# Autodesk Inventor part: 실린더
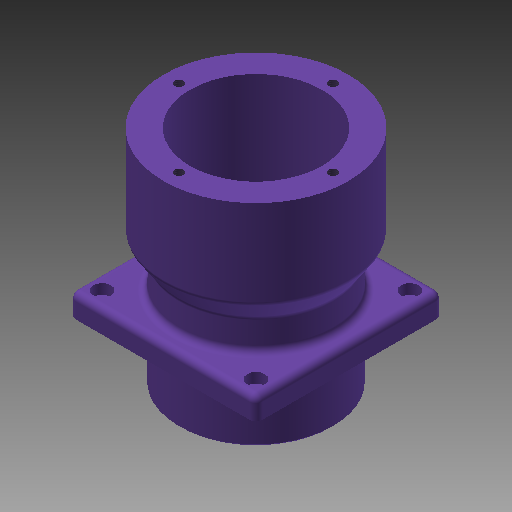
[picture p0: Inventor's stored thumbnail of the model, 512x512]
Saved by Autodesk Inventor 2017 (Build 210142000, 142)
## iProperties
Created: 2016-11
Part Number: 실린더
Material: 알루미늄 6061
Document SubType Name: Modeling
Designer: mduedu
Density: 2.71 g/cm^3
Mass: 568.286 g
Surface Area: 557.364 cm^2
Volume: 209.7 cm^3
Appearance: 보라색
Author: mduedu
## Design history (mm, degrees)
sketch "스케치1"
  geometry: L1 (0, 0)-(0, 101); L2 (30, 0)-(30, 101); L3 (30, 101)-(42, 101); L4 (42, 101)-(42, 61); L5 (42, 61)-(35, 51); L6 (35, 51)-(35, 0); L7 (35, 0)-(30, 0)
  constraints: 14 end point, 4 parallel, 2 horizontal alignment, 1 perpendicular, 1 vertical
  dimensions: "d0" = 101 distance of L1.start L1.end; "d1" = 60 diameter of L2.end L1; "d2" = 84 diameter of L3.end L1; "d3" = 70 diameter of L6.end L1; "d4" = 40 distance of L3.end L4.end; "d5" = 50 vertical distance of L5.end L3.end
revolve "회전1" sketch "스케치1" stored, may be unused: angle "d6" = 90 deg
node "작업 평면1"
sketch "스케치2"
  geometry: L1 (-42.5, -42.5)-(42.5, -42.5); L2 (42.5, -42.5)-(42.5, 42.5); L3 (42.5, 42.5)-(-42.5, 42.5); L4 (-42.5, 42.5)-(-42.5, -42.5); L5 (-42.5, -42.5)-(42.5, 42.5); L6 (42.5, -42.5)-(-42.5, 42.5); C1 r 35 at (0, 0) reference; C2 r 35 at (0, 0); 1 further point
  constraints: 12 end point, 2 midpoint, 2 parallel, 2 perpendicular, 1 centre point, 1 coincident, 1 concentric, 1 horizontal
  dimensions: "d8" = 85 distance of L2.end L3.end
extrude "돌출1" join sketch "스케치2" distance "d10" = 10; taper "d11" = 0 deg
fillet "모깎기1" dims "d12" = 3
fillet "모깎기2" dims "d13" = 3
chamfer "모따기1" distance "d14" = 1; stored, may be unused: second distance "d15" = 2, angle "d16" = 45 deg
chamfer "모따기2" distance "d17" = 5; stored, may be unused: second distance "d18" = 2, angle "d19" = 15 deg
sketch "스케치3"
  geometry: L1 (-35, -35)-(35, -35); L2 (35, -35)-(35, 35); L3 (35, 35)-(-35, 35); L4 (-35, 35)-(-35, -35); L5 (-35, -35)-(35, 35); L6 (35, -35)-(-35, 35); 5 further points
  constraints: 12 end point, 4 coincident, 2 midpoint, 2 parallel, 1 horizontal, 1 perpendicular
  dimensions: "d20" = 70 distance of L3.end L2.end; "d21" = 70 distance of L2.end L1.end
sketch "스케치4"
  geometry: 4 further points
  constraints: 4 other
hole "구멍1" sketch "스케치4" at (-35, 35), (35, 35), (35, -35), (-35, -35) diameter "d22" = 4.5; stored, may be unused: countersink angle "d26" = 90 deg, drill point angle "d28" = 0 deg; dims "d23" = 6, "d24" = 8, "d25" = 4.6, "d27" = 8
sketch "스케치5"
  geometry: 4 further points
  constraints: 4 other
hole "구멍2" sketch "스케치5" at (0, -35), (35, 0), (-35, 0), (0, 35) diameter "d29" = 4.134; stored, may be unused: countersink angle "d33" = 90 deg, drill point angle "d35" = 120 deg; dims "d30" = 12, "d31" = 4, "d32" = 2, "d34" = 15
node "솔리드1"
other parameters: "d7" = -27
